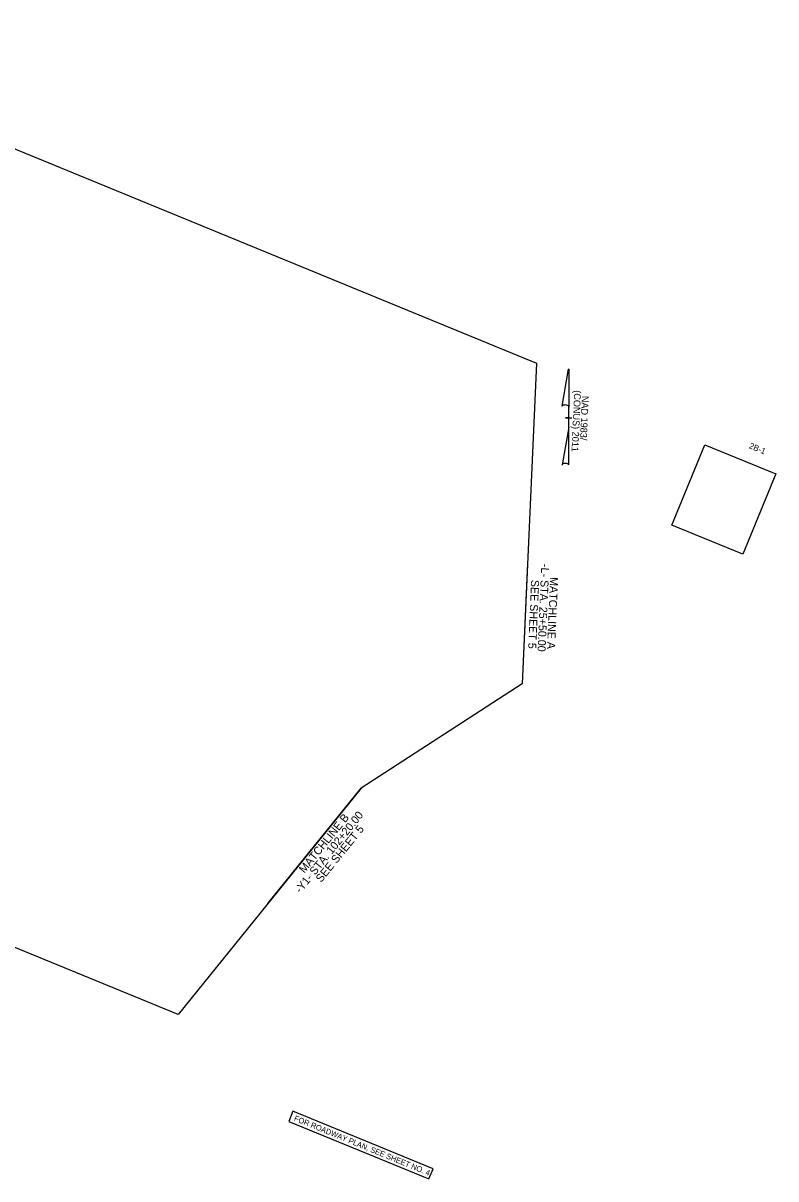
# Model space of a CAD drawing. Extents: x 2090082 to 2091964, y 863291 to 864736.
# Drawn here: x 2091023 to 2091964, y 863291 to 864736 of the extents above; entities that cross this region are included whole.
import ezdxf

# ---------------------------------------------------------------- set-up
doc = ezdxf.new("R2010")
doc.units = 0
for name, color, linetype in [('Matchline', 7, 'Continuous'), ('Matchline Text', 7, 'Continuous'), ('Prop DSN Text', 7, 'Continuous'), ('Prop Grid Mask', 7, 'Continuous'), ('Prop North Arrow for Plan Sheets CELL', 7, 'Continuous'), ('Prop North Arrow NAD83 for Plan Sheets CELL', 7, 'Continuous'), ('Scratch_Level_6', 7, 'Continuous'), ('Sheet Clip Boundary CELL', 7, 'Continuous'), ('Sheet Data Field CELL', 7, 'Continuous')]:
    doc.layers.add(name, color=color, linetype=linetype)

msp = doc.modelspace()

# ---------------------------------------------------------------- linework, layer by layer
at = {"layer": 'Matchline'}
for p, q in [((2091653.3, 864060.7), (2091646.7, 863909.8)), ((2091328.8, 863635.3), (2091445.4, 863779.5))]:
    msp.add_line(p, q, dxfattribs=at)
at = {"layer": 'Prop Grid Mask'}
msp.add_lwpolyline([(2091354.8, 863363.1), (2091530, 863291.2), (2091535.2, 863303.9), (2091360.1, 863375.9)], close=True, dxfattribs=at)
at = {"layer": 'Prop North Arrow for Plan Sheets CELL'}
for p, q in [((2091696.4, 864257), (2091704.6, 864303.4)), ((2091704.7, 864303.4), (2091704.6, 864303.4)), ((2091704.7, 864303.4), (2091704.6, 864303.4)), ((2091704.7, 864303.4), (2091704.7, 864255.6)), ((2091704.7, 864230.8), (2091704.7, 864257)), ((2091704.7, 864255.6), (2091704.7, 864256.9)), ((2091700.7, 864242.4), (2091700.6, 864242.4)), ((2091700.7, 864242.4), (2091708.7, 864242.4)), ((2091704.2, 864242.4), (2091700.7, 864242.4)), ((2091704.7, 864230.8), (2091696.3, 864183.5)), ((2091704.7, 864183.7), (2091704.7, 864230.8))]:
    msp.add_line(p, q, dxfattribs=at)
for centre, start_param, end_param in [((2091700.6, 864256.5), 0.216388, 2.908219), ((2091700.6, 864183.4), 0.201328, 3.141593)]:
    msp.add_ellipse(centre, major_axis=(4.23, -0.03), ratio=0.461098, start_param=start_param, end_param=end_param, dxfattribs=at)
at = {"layer": 'Scratch_Level_6'}
msp.add_lwpolyline([(2091874.7, 864208.6), (2091963.5, 864172.2), (2091922.3, 864071.8), (2091833.5, 864108.3)], close=True, dxfattribs=at)
at = {"layer": 'Sheet Clip Boundary CELL'}
msp.add_lwpolyline([(2090629.6, 864735.7), (2091664.4, 864310.6), (2091646.7, 863909.8), (2091445.4, 863779.5), (2091216.6, 863496.5), (2090278.8, 863881.6)], close=True, dxfattribs=at)

# ---------------------------------------------------------------- texts
at = {"layer": 'Matchline Text'}
for s, rotation, p in [('-L- STA. 25+50.00', 267.4725, (2091670.5, 864059.9)), ('SEE SHEET 5', 267.4725, (2091657.8, 864040.1)), ('MATCHLINE A', 267.4725, (2091681.5, 864043.5)), ('-Y1- STA. 102+20.00', 51.0406, (2091369.4, 863647.6)), ('MATCHLINE B', 51.0406, (2091374.4, 863672.6)), ('SEE SHEET 5', 51.0406, (2091395.4, 863661))]:
    msp.add_text(s, height=10, rotation=rotation, dxfattribs=at).set_placement(p)
at = {"layer": 'Prop DSN Text'}
msp.add_text('FOR ROADWAY PLAN, SEE SHEET NO. 4', height=7, rotation=337.6724, dxfattribs=at).set_placement((2091360.8, 863364.3))
at = {"layer": 'Prop North Arrow NAD83 for Plan Sheets CELL'}
for s, p in [('(CONUS) 2011', (2091711.5, 864277)), ('NAD 1983/ ', (2091721.2, 864270))]:
    msp.add_text(s, height=8.5, rotation=267.5603, dxfattribs=at).set_placement(p)
at = {"layer": 'Sheet Data Field CELL'}
msp.add_text('2B-1', height=7.5, rotation=337.6724, dxfattribs=at).set_placement((2091929.4, 864204.7))

doc.saveas('drawing.dxf')
